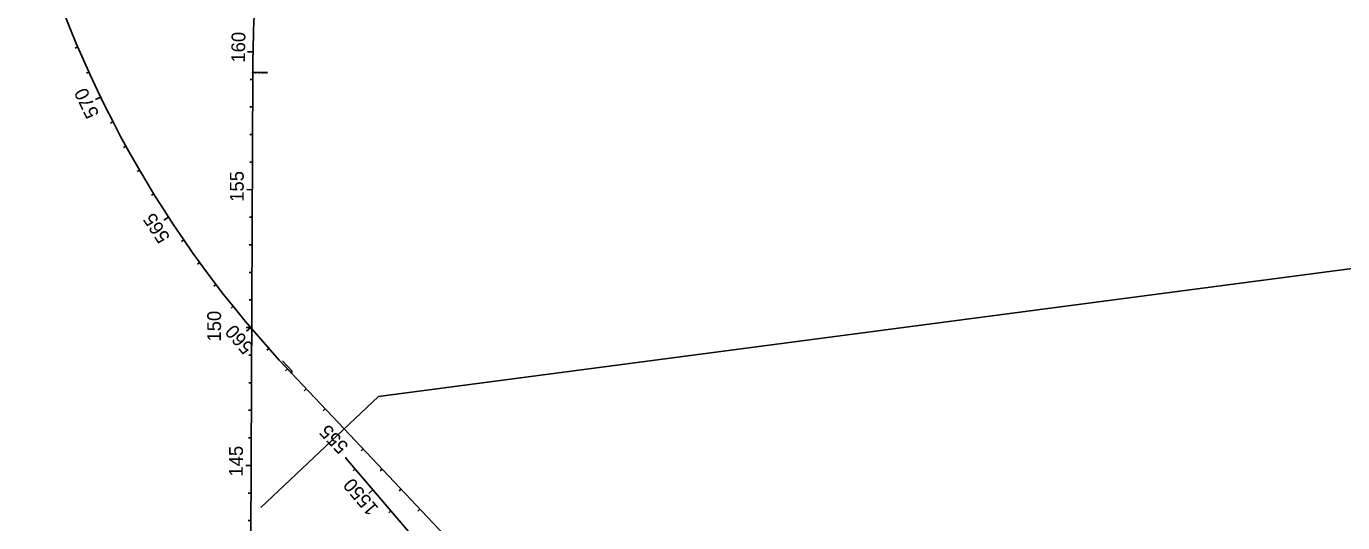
# Model space of a CAD drawing. Extents: x 448091 to 665917, y 1461380 to 1587607.
# Drawn here: x 478731 to 483504, y 1571956 to 1573756 of the extents above; entities that cross this region are included whole.
import ezdxf

# ---------------------------------------------------------------- set-up
doc = ezdxf.new("R2010")
doc.units = 0
for name, color, linetype in [('AttenuatorTM', 7, 'Continuous'), ('BarrierWall_ep', 7, 'Continuous'), ('BillboardVeg', 7, 'Continuous'), ('BillboardZone', 7, 'Continuous'), ('BLSurvey_dp', 7, 'Continuous'), ('BLSurveyCntrl_ep', 7, 'Continuous'), ('BLSurveyField_ep', 7, 'Continuous'), ('BLSurveySymbl_ep', 7, 'Continuous')]:
    doc.layers.add(name, color=color, linetype=linetype)

msp = doc.modelspace()

# ---------------------------------------------------------------- linework, layer by layer
at = {"layer": 'AttenuatorTM'}
for p, q in [((479552.5, 1573588.6), (479605, 1573588.3)), ((479695.6, 1572504.3), (479659.3, 1572542.7)), ((479691.4, 1572500.4), (479695.6, 1572504.3))]:
    msp.add_line(p, q, dxfattribs=at)
for centre, radius in [((479551.8, 1573588.6), 0.75), ((479690.6, 1572499.7), 1), ((479889.3, 1572190.5), 1)]:
    msp.add_circle(centre, radius, dxfattribs=at)
at = {"layer": 'BarrierWall_ep'}
for p, q in [((480007.6, 1572413.4), (490159.9, 1573748.2)), ((479581.5, 1572010.7), (480007.6, 1572413.4))]:
    msp.add_line(p, q, dxfattribs=at)
at = {"layer": 'BillboardVeg'}
for p, q in [((479883.3, 1572295.9), (479690.6, 1572499.7)), ((480957.2, 1571159.4), (479883.3, 1572295.9))]:
    msp.add_line(p, q, dxfattribs=at)
msp.add_arc((482597.8, 1575247.1), 4000, 194.8079, 223.3814, dxfattribs=at)
at = {"layer": 'BLSurvey_dp'}
for p, q in [((478917.1, 1573681.1), (478907.9, 1573677.2)), ((478957.4, 1573589.6), (478948.3, 1573585.4)), ((479000, 1573499.1), (478982, 1573490.4)), ((479044.8, 1573409.7), (479035.9, 1573405.1)), ((479091.8, 1573321.5), (479083.1, 1573316.7)), ((479141.1, 1573234.4), (479132.4, 1573229.4)), ((479192.5, 1573148.6), (479184, 1573143.4)), ((479246, 1573064.2), (479229.2, 1573053.3)), ((479301.6, 1572981.1), (479293.4, 1572975.4)), ((479359.3, 1572899.4), (479351.2, 1572893.5)), ((479419, 1572819.2), (479411, 1572813.1)), ((479480.7, 1572740.5), (479472.9, 1572734.2)), ((479544.3, 1572663.3), (479529, 1572650.4)), ((479609.8, 1572587.8), (479602.4, 1572581.1)), ((479677.2, 1572513.9), (479669.9, 1572507.1)), ((479745.9, 1572441.2), (479738.6, 1572434.3)), ((479814.6, 1572368.5), (479807.3, 1572361.7)), ((479883.3, 1572295.9), (479868.7, 1572282.1)), ((479951.9, 1572223.2), (479944.7, 1572216.3)), ((480020.6, 1572150.5), (480013.4, 1572143.6)), ((480089.3, 1572077.8), (480082.1, 1572071)), ((480158, 1572005.1), (480150.7, 1571998.3))]:
    msp.add_line(p, q, dxfattribs=at)
at = {"layer": 'BLSurveyCntrl_ep'}
for p, q in [((479544.9, 1571894.1), (479551.8, 1573588.6)), ((480116, 1571923.9), (479889.3, 1572190.5))]:
    msp.add_line(p, q, dxfattribs=at)
msp.add_arc((485281.4, 1573565.4), 5729.6, 177.71823, 179.76808, dxfattribs=at)
at = {"layer": 'BLSurveyField_ep'}
for p, q in [((479552.6, 1573663.5), (479532.6, 1573663.8)), ((479551.7, 1573563.5), (479541.7, 1573563.5)), ((479551.3, 1573463.5), (479541.3, 1573463.5)), ((479550.9, 1573363.5), (479540.9, 1573363.6)), ((479550.5, 1573263.5), (479540.5, 1573263.6)), ((479550.1, 1573163.5), (479530.1, 1573163.6)), ((479549.7, 1573063.5), (479539.7, 1573063.6)), ((479549.2, 1572963.5), (479539.2, 1572963.6)), ((479548.8, 1572863.5), (479538.8, 1572863.6)), ((479548.4, 1572763.5), (479538.4, 1572763.6)), ((479548, 1572663.5), (479528, 1572663.6)), ((479547.6, 1572563.5), (479537.6, 1572563.6)), ((479547.2, 1572463.5), (479537.2, 1572463.6)), ((479546.8, 1572363.5), (479536.8, 1572363.6)), ((479546.4, 1572263.5), (479536.4, 1572263.6)), ((479546, 1572163.5), (479526, 1572163.6)), ((479922.8, 1572151.1), (479915.2, 1572144.6)), ((479545.6, 1572063.5), (479535.6, 1572063.6)), ((479987.6, 1572074.9), (479972.4, 1572061.9)), ((479545.2, 1571963.5), (479535.2, 1571963.6)), ((480052.4, 1571998.7), (480044.8, 1571992.2))]:
    msp.add_line(p, q, dxfattribs=at)

# ---------------------------------------------------------------- texts
at = {"layer": 'AttenuatorTM'}
for s, rotation, p in [('PC STA. 159+25.05', 359.7681, (479562.3, 1573582.9)), ('PC STA. 557+80.43', 133.3814, (479693.5, 1572504.7))]:
    msp.add_text(s, height=3.5, rotation=rotation, dxfattribs=at).set_placement(p)
at = {"layer": 'BillboardZone'}
for s, rotation, p in [('570', 115.9124, (478995.8, 1573437.3)), ('565', 123.0744, (479253.8, 1572990.5)), ('560', 130.2363, (479557.6, 1572593.5)), ('555', 133.3814, (479901.9, 1572234.8))]:
    msp.add_text(s, height=50, rotation=rotation, dxfattribs=at).set_placement(p)
at = {"layer": 'BLSurveySymbl_ep'}
for s, rotation, p in [('160', 89.0186, (479523.3, 1573623.8)), ('155', 89.7681, (479518.7, 1573119.4)), ('150', 89.7681, (479436.4, 1572612.7)), ('145', 89.7681, (479515.6, 1572123.1)), ('1550', 130.3814, (480010.2, 1572008.7))]:
    msp.add_text(s, height=50, rotation=rotation, dxfattribs=at).set_placement(p)

doc.saveas('drawing.dxf')
